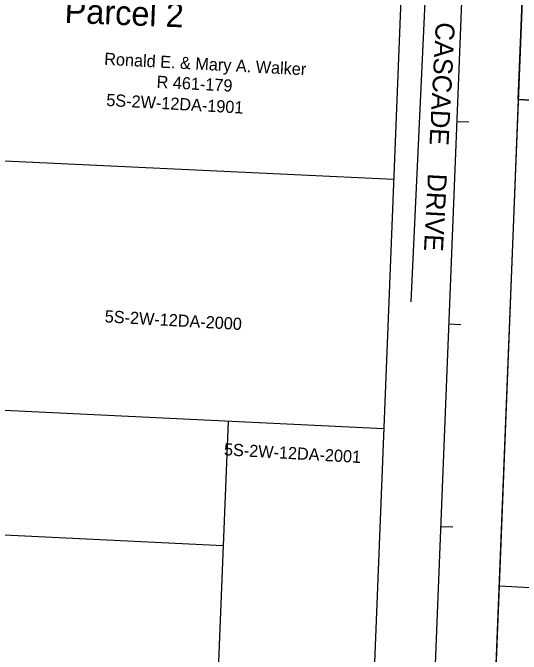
# Model space of a CAD drawing. Extents: x 7581380 to 7602708, y 543740 to 556109.
# Drawn here: x 7591225.9 to 7591476.9, y 549682.6 to 549999.1 of the extents above; entities that cross this region are included whole.
import ezdxf

# ---------------------------------------------------------------- set-up
doc = ezdxf.new("R2010")
doc.units = 0
for name, color, linetype in [('E_RDWY_ROAD_NameTx', 7, 'Continuous'), ('E_SURV_ALIGN_MainTx', 7, 'Continuous'), ('E_SURV_ALIGN_MinorTx', 7, 'Continuous'), ('E_SURV_BNDRY_CROW', 7, 'Continuous'), ('E_SURV_BNDRY_GovDLCLine', 7, 'Continuous'), ('E_SURV_BNDRY_OwnerTx', 7, 'Continuous'), ('E_SURV_BNDRY_Property', 7, 'Continuous'), ('E_SURV_BNDRY_SubdivisionTx', 7, 'Continuous'), ('E_Surv_Bndry_Tax_Lot', 7, 'Continuous'), ('P_RW_FILE_AreaShapeRemain', 7, 'Continuous')]:
    doc.layers.add(name, color=color, linetype=linetype)

msp = doc.modelspace()

# ---------------------------------------------------------------- linework, layer by layer
at = {"layer": 'E_SURV_ALIGN_MainTx'}
msp.add_lwpolyline([(7591436.41, 550156.12), (7591422.43, 549856.45)], dxfattribs=at)
at = {"layer": 'E_SURV_ALIGN_MinorTx'}
for points in [[(7591451.04, 549945.08), (7591445.05, 549945.31)], [(7591447.07, 549845.15), (7591441.08, 549845.39)], [(7591443.1, 549745.23), (7591437.1, 549745.47)]]:
    msp.add_lwpolyline(points, dxfattribs=at)
at = {"layer": 'E_SURV_BNDRY_CROW'}
for points in [[(7591421.55, 550109.61), (7591397, 549491.91)], [(7591481.56, 550108.65), (7591441.7, 549105.87)]]:
    msp.add_lwpolyline(points, dxfattribs=at)
at = {"layer": 'E_SURV_BNDRY_GovDLCLine'}
msp.add_lwpolyline([(7591452.99, 550145.16), (7591385.11, 548437.45)], dxfattribs=at)
at = {"layer": 'E_SURV_BNDRY_Property'}
for p, q in [((7591413.89, 549916.79), (7591214.18, 549926.34)), ((7591409, 549793.89), (7591209.32, 549803.44)), ((7591329.7, 549736.11), (7591206.89, 549741.99))]:
    msp.add_line(p, q, dxfattribs=at)
for points in [[(7591475.51, 549956.39), (7591795.88, 549939.19)], [(7591332.14, 549797.56), (7591327.25, 549674.64)], [(7591465.97, 549716.25), (7591930.21, 549691.61)]]:
    msp.add_lwpolyline(points, dxfattribs=at)
at = {"layer": 'P_RW_FILE_AreaShapeRemain'}
for points in [[(7591792.96, 549939.34), (7591475.51, 549956.39), (7591480.97, 550093.66)], [(7591792.99, 549939.34), (7591475.51, 549956.39), (7591465.97, 549716.25), (7591456.86, 549487.26), (7591773.7, 549469.66), (7591783.29, 549699.41), (7591930.21, 549691.61), (7591933.69, 549765.02)]]:
    msp.add_lwpolyline(points, dxfattribs=at)

# ---------------------------------------------------------------- texts
at = {"layer": 'E_RDWY_ROAD_NameTx'}
msp.add_text('CASCADE    DRIVE', height=9.4, rotation=267.0115, dxfattribs=at).set_placement((7591434.79, 549994.64))
at = {"layer": 'E_SURV_BNDRY_OwnerTx'}
for s, p in [('Ronald E. & Mary A. Walker', (7591270.88, 549973.5)), ('R 461-179', (7591296.75, 549962.14))]:
    msp.add_text(s, height=6, rotation=357, dxfattribs=at).set_placement(p)
at = {"layer": 'E_SURV_BNDRY_SubdivisionTx'}
msp.add_text('Parcel 2', height=12, rotation=357.7534, dxfattribs=at).set_placement((7591251.25, 549994.23))
at = {"layer": 'E_Surv_Bndry_Tax_Lot'}
for s, p in [('5S-2W-12DA-1901', (7591271.9, 549953.2)), ('5S-2W-12DA-2000', (7591271.12, 549846.39)), ('5S-2W-12DA-2001', (7591330, 549780.76))]:
    msp.add_text(s, height=6, rotation=356.7425, dxfattribs=at).set_placement(p)

doc.saveas('drawing.dxf')
